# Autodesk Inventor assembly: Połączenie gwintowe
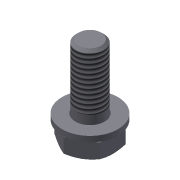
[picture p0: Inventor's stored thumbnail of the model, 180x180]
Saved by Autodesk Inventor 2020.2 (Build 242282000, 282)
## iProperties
Created: 2010-09
Part Number: Połączenie gwintowe
Document SubType Name: Assembly
Designer: F.Stasiak
ClientObjectVersion: 1
Manager: www.cadconsulting.pl
Company: Fabian Stasiak CAD Consulting
Author: F.Stasiak
Subject: Zbiór ćwiczeń. Autodesk Inventor 2020. Kurs podstawowy
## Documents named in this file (3)
- C:\2020_Kurs_podstawowy\R9 Zarządzanie plikami\369-000\Design Accelerator\Połączenie gwintowe2.iam
- C:\2020_Kurs_podstawowy\Zasoby\Content Center Files\pl-PL\ISO 7089\ISO 7089 - 8 - 140 HV(1).ipt
- C:\2020_Kurs_podstawowy\Zasoby\Content Center Files\pl-PL\ISO 4017(1)\ISO 4017 - M8 x 20ISO.ipt
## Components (2 placed, 2 different names)
1. ISO 7089 8 - 140 HV:1
2. ISO 4017 M8 x 20:1
